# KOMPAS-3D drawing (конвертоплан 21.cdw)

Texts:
  Текст на чертеже
  Размерные надписи
  Шероховатость
  Линия-выноска #1
  Линия-выноска #2
  Линия-выноска #3
  Отклонения формы и база
  Заголовок таблицы
  Ячейка таблицы
  Стрелка вида
  Обозначение изменения
  Фигурная скобка
  Номер узла
  Марка координационной оси
  VRCB
  Выносная надпись
  Обозначение узла
  Марка/позиционное обозначение с линией-выноской
  Марка/позиционное обозначение на линии
  Марка/позиционное обозначение без линии-выноски
  ыыы
  чертеж
  Группа 1
Dimensions and other numbers on the sheet: 7; 1; 0; 2; 3; 4; 5; 6; 8; 9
